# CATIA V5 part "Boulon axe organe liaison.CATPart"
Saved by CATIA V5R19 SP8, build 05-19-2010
Part number: Boulon axe organe liaison
Bounding box of the stored display mesh (mm): x -4.499 to 4.499, y -4.499 to 4.499, z 0 to 5
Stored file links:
  G:\EU_thinkMotion\CFAO_2010\MMS_groupe2\MMS_groupe2\A reprendre\rbouchet\rbouchet_Catia\Boulon axe organe liaison.CATPart
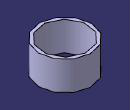
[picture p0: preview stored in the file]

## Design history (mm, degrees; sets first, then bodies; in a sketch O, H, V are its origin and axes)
Body1 (main body)
  Sketch1 on yz-plane, origin (0, 0, 0), H (0, 1, 0), V (0, 0, 1)
    line L1 (4, 5) -> (4.5, 5)
    line L2 (4.5, 5) -> (4.5, 0)
    line L3 (4.5, 0) -> (4, 0)
    line L4 (4, 0) -> (4, 5)
    length L2 = 5
    length L1 = 0.5
    distance L4 V = 4
    distance L3 H = 0
    horizontal: L1 H, L3 H
    vertical: L2 V, L4 V
  Shaft1: profile Sketch1, axis Sketch1.V, angle 360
